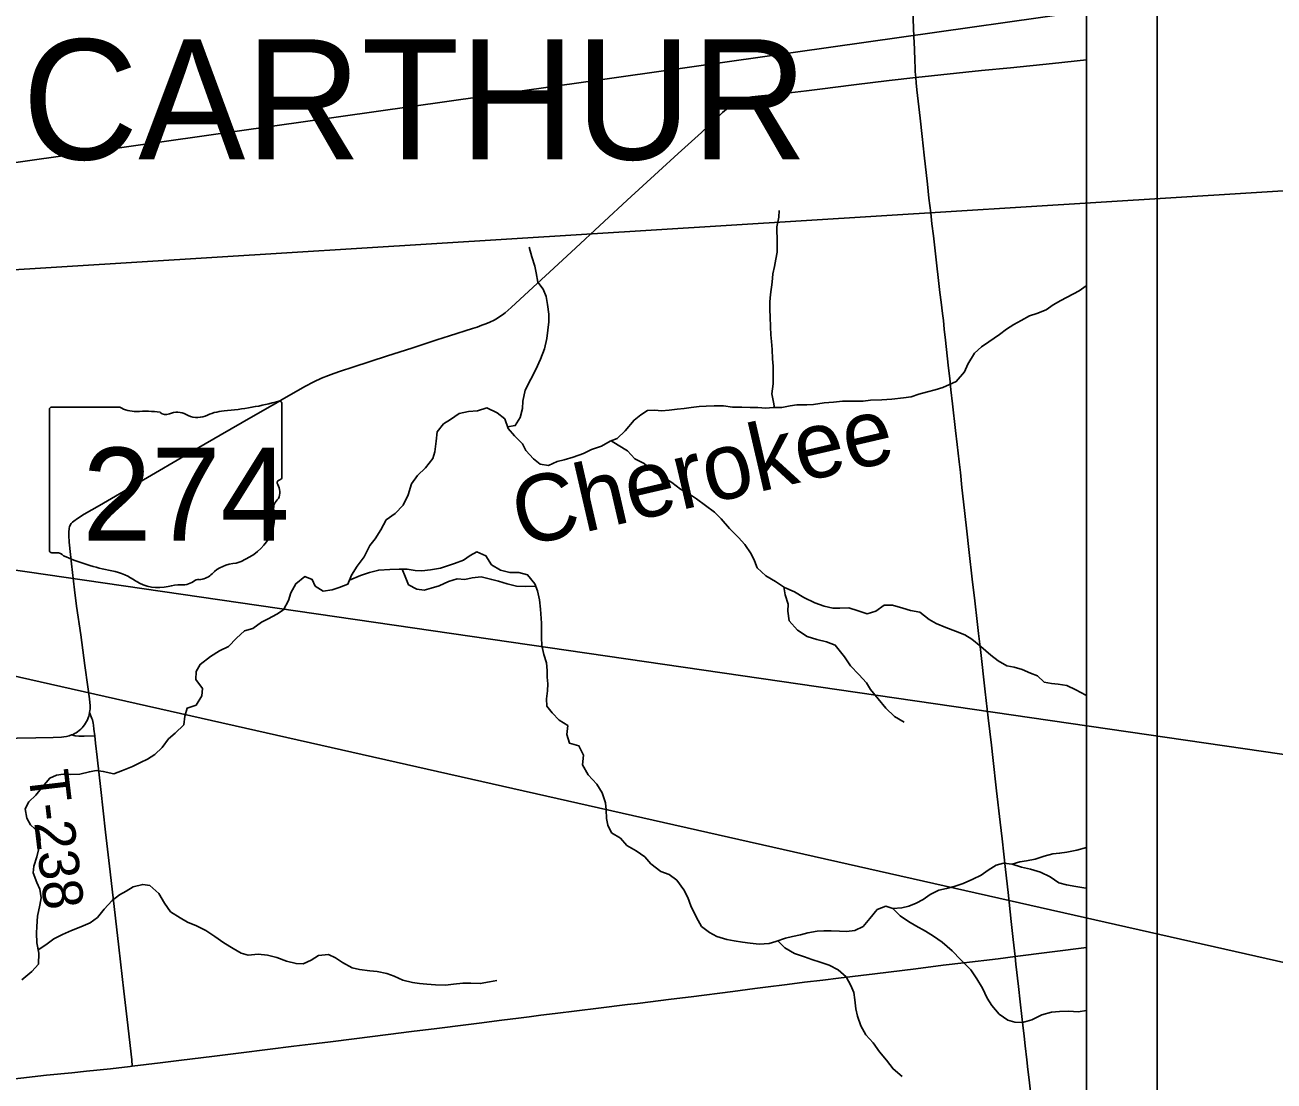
# Model space of a CAD drawing. Extents: x 0 to 34, y -5.4 to 22.
# Drawn here: x 7.394 to 9.166, y 16.492 to 17.991 of the extents above; entities that cross this region are included whole.
import ezdxf

# ---------------------------------------------------------------- set-up
doc = ezdxf.new("R2010")
doc.units = 0
for name, color, linetype in [('GM_X_County_Road', 7, 'Continuous'), ('GM_X_Minor_River', 7, 'Continuous'), ('GM_X_Minor_River_Text', 7, 'Continuous'), ('GM_X_Rail_Line', 7, 'Continuous'), ('GM_X_State_Location', 7, 'Continuous'), ('GM_X_State_Route', 7, 'Continuous'), ('GM_X_State_Shield', 7, 'Continuous'), ('GM_X_Township_Road', 7, 'Continuous'), ('GM_X_Township_Road_Text', 7, 'Continuous'), ('GM_X_Township_Text', 7, 'Continuous'), ('SH_Data', 7, 'Continuous')]:
    doc.layers.add(name, color=color, linetype=linetype)

msp = doc.modelspace()

# ---------------------------------------------------------------- linework, layer by layer
at = {"layer": 'GM_X_County_Road'}
msp.add_lwpolyline([(8.8238, 16.4466), (8.8184, 16.4941), (8.8168, 16.5086), (8.8152, 16.5225), (8.813, 16.542), (8.8114, 16.5558), (8.8096, 16.5717), (8.8082, 16.5836), (8.8058, 16.6046), (8.8035, 16.6265), (8.7997, 16.658), (8.7986, 16.6688), (8.796, 16.6929), (8.7931, 16.7188), (8.7886, 16.7596), (8.7851, 16.7923), (8.7803, 16.8361), (8.7776, 16.8595), (8.7724, 16.9039), (8.7669, 16.9514), (8.7649, 16.9687), (8.7603, 17.0076), (8.756, 17.0446), (8.7494, 17.1045), (8.7467, 17.1273), (8.7436, 17.1526), (8.7423, 17.1652), (8.7414, 17.1736), (8.7377, 17.2044), (8.7334, 17.242), (8.7297, 17.2766), (8.7255, 17.3141), (8.7232, 17.3346), (8.7209, 17.3557), (8.7191, 17.371), (8.7163, 17.3954), (8.7141, 17.4154), (8.7096, 17.4531), (8.7075, 17.4731), (8.7058, 17.4889), (8.7046, 17.4997), (8.7037, 17.508), (8.6998, 17.5432), (8.6981, 17.5589), (8.6968, 17.5711), (8.6956, 17.5814), (8.6936, 17.5973), (8.6919, 17.6111), (8.685, 17.6704), (8.6826, 17.6914), (8.6806, 17.7083), (8.6788, 17.724), (8.6764, 17.745), (8.6743, 17.7647), (8.6695, 17.806), (8.6665, 17.8326), (8.6637, 17.8585), (8.6593, 17.8987), (8.6584, 17.9085), (8.6578, 17.916), (8.6575, 17.9198), (8.657, 17.9248), (8.6567, 17.9301), (8.6563, 17.9396), (8.6557, 17.9564), (8.655, 17.9744), (8.6532, 18.0224)], dxfattribs=at)
at = {"layer": 'GM_X_Minor_River'}
for points in [[(8.4572, 17.4479), (8.4555, 17.4578), (8.4534, 17.4673), (8.4551, 17.4813), (8.4553, 17.4957), (8.4551, 17.5067), (8.4545, 17.517), (8.454, 17.5303), (8.4527, 17.5413), (8.4521, 17.5512), (8.4515, 17.5622), (8.451, 17.5763), (8.4508, 17.5865), (8.4506, 17.5979), (8.4515, 17.6081), (8.4537, 17.6259), (8.455, 17.6377), (8.4571, 17.6479), (8.4591, 17.6585), (8.4608, 17.6683), (8.461, 17.682), (8.4606, 17.704), (8.4635, 17.718), (8.4637, 17.7275)], [(8.0785, 17.4206), (8.0893, 17.4223), (8.0963, 17.4335), (8.0996, 17.4464), (8.1001, 17.457), (8.1034, 17.4725), (8.1112, 17.4879), (8.1183, 17.5019), (8.1253, 17.5165), (8.1308, 17.5313), (8.1341, 17.5456), (8.1371, 17.5695), (8.1369, 17.5805), (8.1349, 17.5942), (8.1332, 17.6056), (8.1288, 17.6159), (8.1214, 17.6259), (8.119, 17.6389), (8.1169, 17.6484), (8.1126, 17.6617), (8.109, 17.6755)], [(8.115, 17.3751), (8.1248, 17.3674), (8.1365, 17.3657), (8.1487, 17.3712), (8.1585, 17.3736), (8.1715, 17.3772), (8.1863, 17.3827), (8.1974, 17.3885), (8.2115, 17.3932), (8.2241, 17.4002), (8.234, 17.4039), (8.2455, 17.4147), (8.2579, 17.43), (8.2674, 17.4375), (8.277, 17.4437), (8.2872, 17.444), (8.297, 17.443), (8.3077, 17.444), (8.319, 17.4453), (8.3289, 17.4467), (8.3391, 17.448), (8.3501, 17.4493), (8.3604, 17.4499), (8.3717, 17.4501), (8.3846, 17.4503), (8.3974, 17.4485), (8.4107, 17.4483), (8.4228, 17.4477), (8.4334, 17.4479), (8.4451, 17.447), (8.4553, 17.4479), (8.4674, 17.4481), (8.4792, 17.4502), (8.4887, 17.4515), (8.503, 17.4517), (8.5125, 17.4523), (8.5277, 17.4543), (8.541, 17.4556), (8.5535, 17.4569), (8.5667, 17.457), (8.583, 17.4571), (8.5936, 17.4581), (8.6095, 17.4589), (8.6235, 17.4598), (8.6402, 17.4618), (8.6512, 17.4632), (8.6622, 17.4668), (8.6744, 17.47), (8.685, 17.4728), (8.6961, 17.4761), (8.7151, 17.4849), (8.7267, 17.4987), (8.7314, 17.5092), (8.7408, 17.525), (8.7508, 17.534), (8.7615, 17.541), (8.7764, 17.5517), (8.7864, 17.5592), (8.7967, 17.5658), (8.807, 17.5713), (8.8192, 17.578), (8.8295, 17.5812), (8.8428, 17.5867), (8.8528, 17.5937), (8.8635, 17.5996), (8.8894, 17.6136), (8.8994, 17.6206), (8.9, 17.621)], [(7.3889, 16.6359), (7.4031, 16.6475), (7.4127, 16.6579), (7.4134, 16.6738), (7.4102, 16.6883), (7.41, 16.702), (7.4106, 16.7115), (7.4112, 16.7263), (7.4145, 16.7418), (7.4165, 16.752), (7.4148, 16.7645), (7.4105, 16.7741), (7.4054, 16.7875), (7.4063, 16.7973), (7.4103, 16.8102), (7.4127, 16.8204), (7.4152, 16.8344), (7.4139, 16.8443), (7.4016, 16.8555), (7.3964, 16.8654), (7.394, 16.8784), (7.3991, 16.8886), (7.4091, 16.8979), (7.4183, 16.9095), (7.4288, 16.9218), (7.4383, 16.9262), (7.4478, 16.9276), (7.4587, 16.927), (7.4712, 16.9276), (7.4849, 16.9311), (7.4948, 16.9329), (7.5046, 16.9315), (7.5197, 16.9283), (7.5319, 16.933), (7.546, 16.9384), (7.5574, 16.9443), (7.5673, 16.9491), (7.5777, 16.9554), (7.5884, 16.9654), (7.5973, 16.9778), (7.6069, 16.986), (7.6188, 16.9975), (7.6202, 17.0097), (7.6238, 17.0214), (7.6363, 17.0257), (7.6445, 17.0389), (7.6454, 17.0491), (7.6361, 17.0618), (7.6363, 17.0732), (7.6422, 17.0833), (7.6567, 17.0948), (7.6697, 17.1026), (7.6823, 17.1088), (7.6935, 17.1204), (7.705, 17.1308), (7.7168, 17.1341), (7.7291, 17.1433), (7.7386, 17.1481), (7.7508, 17.1547), (7.7604, 17.161), (7.7674, 17.1742), (7.771, 17.1851), (7.778, 17.1979), (7.7907, 17.208), (7.8012, 17.204), (7.8056, 17.1944), (7.8168, 17.1874), (7.8297, 17.1891), (7.8392, 17.1923), (7.8518, 17.197), (7.8569, 17.2102), (7.8651, 17.2226), (7.8747, 17.2361), (7.883, 17.2519), (7.8907, 17.2617), (7.8985, 17.2744), (7.9059, 17.2884), (7.9189, 17.2973), (7.9301, 17.3092), (7.9375, 17.3239), (7.9419, 17.3394), (7.9508, 17.3514), (7.9619, 17.3622), (7.9724, 17.3753), (7.9752, 17.3851), (7.9769, 17.3999), (7.9783, 17.4135), (7.9876, 17.4248), (7.9975, 17.4307), (8.0098, 17.4396), (8.023, 17.442), (8.0356, 17.4433), (8.0489, 17.4476), (8.0635, 17.4405), (8.0747, 17.4316), (8.0794, 17.4179), (8.0883, 17.4075), (8.0995, 17.3963), (8.1043, 17.3867), (8.115, 17.3751)], [(8.2256, 17.4008), (8.2353, 17.3944), (8.2484, 17.3862), (8.2588, 17.375), (8.2724, 17.3683), (8.2862, 17.3563), (8.2963, 17.3508), (8.3113, 17.3414), (8.324, 17.3321), (8.3367, 17.3247), (8.3465, 17.3184), (8.3592, 17.3087), (8.3719, 17.2994), (8.3816, 17.2898), (8.3935, 17.2763), (8.4061, 17.2635), (8.415, 17.2535), (8.4243, 17.2404), (8.429, 17.2301), (8.4327, 17.2202), (8.445, 17.209), (8.4585, 17.2011), (8.4716, 17.1926), (8.4855, 17.1862), (8.499, 17.1784), (8.5144, 17.1709), (8.5279, 17.1658), (8.54, 17.1633), (8.5498, 17.1631), (8.5627, 17.1637), (8.5759, 17.1593), (8.5887, 17.1549), (8.6008, 17.1588), (8.6127, 17.1674), (8.6248, 17.1675), (8.6395, 17.1631), (8.65, 17.1599), (8.6632, 17.1574), (8.6767, 17.1473), (8.6868, 17.1414), (8.7004, 17.1355), (8.7139, 17.1307), (8.7274, 17.1252), (8.7372, 17.1193), (8.7499, 17.1088), (8.7641, 17.0965), (8.7745, 17.0883), (8.7869, 17.0813), (8.7975, 17.0796), (8.8088, 17.076), (8.8204, 17.0708), (8.8302, 17.0672), (8.8399, 17.058), (8.8501, 17.0563), (8.8599, 17.0553), (8.872, 17.0536), (8.8847, 17.0473), (8.899, 17.0399), (8.9, 17.0395)], [(7.854, 17.2027), (7.8698, 17.2096), (7.8827, 17.214), (7.8956, 17.2172), (7.9112, 17.2181), (7.9244, 17.2186), (7.9358, 17.2184), (7.9471, 17.2167), (7.9569, 17.2161), (7.969, 17.2174), (7.9831, 17.2199), (7.993, 17.2231), (8.0029, 17.2267), (8.0158, 17.2311), (8.0254, 17.2381), (8.0349, 17.2429), (8.0477, 17.2374), (8.0558, 17.2247), (8.0682, 17.2169), (8.0818, 17.214), (8.0942, 17.2138), (8.1067, 17.2105), (8.1171, 17.1978), (8.1207, 17.1879), (8.1235, 17.175), (8.1252, 17.1616), (8.1264, 17.1419), (8.1266, 17.132), (8.1264, 17.1214), (8.127, 17.1104), (8.1298, 17.0974), (8.1338, 17.0856), (8.1347, 17.0745), (8.1346, 17.0651), (8.1356, 17.0556), (8.135, 17.0457), (8.1337, 17.0343), (8.1343, 17.0241), (8.1417, 17.0145), (8.1514, 17.0044), (8.1638, 16.9966), (8.1624, 16.9837), (8.1664, 16.9715), (8.1796, 16.9679), (8.1862, 16.9548), (8.1848, 16.9408), (8.1929, 16.9266), (8.2052, 16.9135), (8.2125, 16.9013), (8.2176, 16.8871), (8.2182, 16.8772), (8.2188, 16.8647), (8.2205, 16.8552), (8.226, 16.8445), (8.2387, 16.8366), (8.2477, 16.8266), (8.2608, 16.8188), (8.2731, 16.8102), (8.2817, 16.8006), (8.2959, 16.7894), (8.3079, 16.7854), (8.3188, 16.7772), (8.3284, 16.7637), (8.3343, 16.7526), (8.3386, 16.7408), (8.3467, 16.7243), (8.3536, 16.7117), (8.3648, 16.7028), (8.3754, 16.6973), (8.3897, 16.6928), (8.3999, 16.6912), (8.4119, 16.6894), (8.4225, 16.6877), (8.4354, 16.6864), (8.4494, 16.6873), (8.4593, 16.6901), (8.473, 16.6948), (8.4828, 16.6973), (8.4939, 16.6998), (8.5045, 16.7027), (8.5178, 16.7047), (8.5272, 16.7053), (8.5375, 16.7055), (8.5496, 16.7049), (8.5594, 16.7044), (8.5711, 16.7057), (8.583, 16.7116), (8.5926, 16.7228), (8.603, 16.7355), (8.6152, 16.7402), (8.625, 16.737), (8.6379, 16.738), (8.6478, 16.7404), (8.6584, 16.7448), (8.668, 16.7496), (8.6779, 16.757), (8.6905, 16.7629), (8.7012, 16.7653), (8.7122, 16.7682), (8.7247, 16.7725), (8.7385, 16.7788)], [(7.929, 17.2185), (7.9329, 17.2082), (7.9377, 17.1963), (7.9497, 17.1901), (7.9599, 17.1888), (7.9698, 17.1916), (7.9815, 17.1948), (7.9945, 17.2011), (8.0071, 17.2047), (8.0176, 17.2037), (8.0283, 17.2062), (8.0408, 17.2075), (8.0559, 17.2038), (8.0657, 17.2014), (8.0777, 17.1978), (8.0909, 17.1945), (8.1038, 17.1939), (8.1183, 17.1944)], [(8.4702, 17.1935), (8.4725, 17.1819), (8.4765, 17.1686), (8.476, 17.1591), (8.478, 17.1454), (8.4899, 17.1319), (8.5037, 17.1229), (8.5173, 17.1185), (8.5309, 17.1152), (8.5433, 17.1105), (8.5566, 17.0939), (8.5648, 17.0813), (8.577, 17.0689), (8.5878, 17.0573), (8.5933, 17.0477), (8.6041, 17.0343), (8.6152, 17.0212), (8.6275, 17.0096), (8.641, 17.0014)], [(8.7944, 16.7998), (8.8055, 16.803), (8.815, 16.8048), (8.8271, 16.8072), (8.84, 16.8112), (8.8522, 16.8144), (8.8617, 16.8154), (8.8719, 16.8171), (8.886, 16.8199), (8.9, 16.8237)], [(8.7385, 16.7788), (8.7503, 16.7842), (8.7602, 16.7913), (8.7717, 16.7987), (8.782, 16.8012), (8.7944, 16.7998), (8.8076, 16.7958), (8.8204, 16.7929), (8.8347, 16.7885), (8.8483, 16.7818), (8.8606, 16.7736), (8.8715, 16.7704), (8.8848, 16.7683), (8.8991, 16.7661), (8.9, 16.766)], [(7.4123, 16.6785), (7.423, 16.6855), (7.4345, 16.694), (7.4467, 16.7002), (7.4597, 16.7057), (7.4726, 16.7108), (7.4863, 16.7166), (7.4967, 16.7244), (7.506, 16.736), (7.5171, 16.7484), (7.5275, 16.7565), (7.5374, 16.7617), (7.547, 16.7676), (7.5606, 16.7712), (7.5708, 16.7695), (7.5835, 16.7582), (7.5916, 16.7448), (7.6001, 16.7325), (7.6136, 16.7236), (7.6241, 16.7177), (7.6369, 16.7122), (7.65, 16.7059), (7.6631, 16.6973), (7.6759, 16.6883), (7.689, 16.6802), (7.7002, 16.6735), (7.7104, 16.6707), (7.7244, 16.672), (7.7376, 16.6706), (7.7512, 16.6673), (7.7647, 16.6625), (7.7783, 16.6589), (7.7885, 16.6587), (7.7996, 16.6638), (7.8103, 16.6705), (7.8243, 16.6718), (7.8341, 16.667), (7.8442, 16.6604), (7.8581, 16.653), (7.8682, 16.6505), (7.883, 16.6487), (7.8935, 16.6474), (7.9071, 16.6449), (7.9173, 16.641), (7.9297, 16.6354), (7.9436, 16.6318), (7.9534, 16.6308), (7.9636, 16.6295), (7.9761, 16.6286), (7.9905, 16.6283), (8.0019, 16.6296), (8.0151, 16.6313), (8.0265, 16.6311), (8.0397, 16.6305), (8.0526, 16.6329), (8.0633, 16.6347)], [(8.625, 16.737), (8.6354, 16.7266), (8.6474, 16.7184), (8.6579, 16.7126), (8.6714, 16.7047), (8.6827, 16.6977), (8.695, 16.6891), (8.7092, 16.6771), (8.7218, 16.664), (8.7356, 16.6501), (8.7445, 16.637), (8.7522, 16.624), (8.7592, 16.6098), (8.7658, 16.5995), (8.7758, 16.5872), (8.7882, 16.5786), (8.7984, 16.5758), (8.8093, 16.5752), (8.8223, 16.5792), (8.8364, 16.5861), (8.8501, 16.5901), (8.8618, 16.591), (8.8747, 16.5912), (8.8879, 16.5906), (8.8997, 16.5923)], [(8.4619, 16.6911), (8.472, 16.6812), (8.4855, 16.6734), (8.4998, 16.6682), (8.5103, 16.6646), (8.522, 16.661), (8.5348, 16.6566), (8.5475, 16.6499), (8.5587, 16.6402), (8.5657, 16.6276), (8.5697, 16.618), (8.5714, 16.6074), (8.5727, 16.5948), (8.5748, 16.5842), (8.5795, 16.5704), (8.5869, 16.5578), (8.5973, 16.5466), (8.6062, 16.5335), (8.6162, 16.522), (8.6255, 16.5093), (8.6385, 16.4988)]]:
    msp.add_lwpolyline(points, dxfattribs=at)
at = {"layer": 'GM_X_Rail_Line'}
msp.add_lwpolyline([(8.9, 15.5944), (8.9, 19.2127), (8.5201, 19.1691), (7.2315, 19.0156), (6.9054, 18.9823), (6.6792, 18.9603), (6.4496, 18.9373), (6.0045, 18.8908), (5.7334, 18.8597), (5.7313, 18.8595), (5.378, 18.814), (5.096, 18.7806), (5.0255, 18.7742), (4.7505, 18.7432), (3.5131, 18.6037), (3.3669, 18.5872), (3.3607, 18.5226), (3.3599, 18.5136), (3.2432, 17.2942), (3.13, 16.1326)], dxfattribs=at)
at = {"layer": 'GM_X_State_Route'}
msp.add_lwpolyline([(7.3554, 16.9784), (7.4089, 16.9791), (7.4337, 16.9796), (7.4454, 16.9803), (7.4489, 16.9806), (7.4527, 16.9811), (7.4564, 16.9819), (7.4596, 16.9832), (7.462, 16.9841), (7.4639, 16.9852), (7.4662, 16.9864), (7.468, 16.9876), (7.4706, 16.9897), (7.4726, 16.9914), (7.4746, 16.9935), (7.4762, 16.9954), (7.478, 16.9977), (7.4795, 17), (7.4809, 17.0024), (7.4821, 17.0049), (7.4832, 17.0074), (7.4841, 17.0097), (7.4847, 17.012), (7.4852, 17.0149), (7.4857, 17.018), (7.4859, 17.0199), (7.486, 17.0217), (7.4859, 17.0247), (7.485, 17.0345), (7.4828, 17.0517), (7.4787, 17.0819), (7.4726, 17.1255), (7.4667, 17.1661), (7.4639, 17.189), (7.4598, 17.226), (7.4565, 17.2567), (7.4559, 17.2662), (7.4557, 17.2695), (7.4558, 17.2724), (7.4561, 17.2746), (7.4565, 17.2769), (7.4569, 17.2788), (7.4579, 17.281), (7.4592, 17.2832), (7.4611, 17.285), (7.463, 17.2866), (7.4682, 17.2904), (7.4778, 17.2964), (7.4993, 17.309), (7.5391, 17.3319), (7.5789, 17.355), (7.6405, 17.3911), (7.6706, 17.4086), (7.7019, 17.4265), (7.7406, 17.4488), (7.7489, 17.4537), (7.7584, 17.4592), (7.7907, 17.4779), (7.8034, 17.4845), (7.8142, 17.4894), (7.8241, 17.4935), (7.832, 17.4963), (7.8413, 17.4994), (7.8589, 17.5051), (7.9078, 17.5211), (7.9427, 17.5323), (7.9782, 17.5437), (7.9959, 17.5494), (8.0284, 17.5598), (8.0352, 17.5621), (8.0419, 17.5645), (8.0477, 17.5667), (8.0531, 17.5689), (8.0594, 17.5719), (8.0641, 17.5748), (8.0673, 17.577), (8.0712, 17.5796), (8.0748, 17.5824), (8.0791, 17.5858), (8.0837, 17.59), (8.1147, 17.6187), (8.1321, 17.6347), (8.1686, 17.6685), (8.2156, 17.7119), (8.2479, 17.7419), (8.2924, 17.7826), (8.3204, 17.8082), (8.3534, 17.8383), (8.3834, 17.8663), (8.3947, 17.8761), (8.3976, 17.8784), (8.4002, 17.8803), (8.4028, 17.8819), (8.4051, 17.8831), (8.4077, 17.8842), (8.4098, 17.8852), (8.4121, 17.8861), (8.4144, 17.8869), (8.4168, 17.8875), (8.4188, 17.8879), (8.4251, 17.8886), (8.4573, 17.892), (8.4783, 17.8944), (8.5024, 17.8972), (8.5215, 17.8996), (8.5698, 17.9058), (8.6197, 17.9118), (8.6578, 17.916), (8.7511, 17.9259), (8.7919, 17.93), (8.8519, 17.9361), (8.9, 17.9411)], dxfattribs=at)
at = {"layer": 'GM_X_State_Shield'}
for p, q in [((7.4285, 17.4451), (7.4285, 17.245)), ((7.5282, 17.4485), (7.4317, 17.4485)), ((7.758, 17.3488), (7.758, 17.4535)), ((7.758, 17.3488), (7.758, 17.3488))]:
    msp.add_line(p, q, dxfattribs=at)
for centre, major_axis, start_param, end_param in [((7.4322, 17.4455), (0.00382, 0), 1.712693, 3.28349), ((7.5512, 17.4717), (0.037, 0), 4.042523, 4.731795), ((7.5635, 17.3362), (0.133, 0), 1.404758, 1.657858), ((7.5937, 17.4465), (0.0107, 0), 3.836095, 5.185415), ((7.6094, 17.4234), (0.0222, 0), 0.950623, 2.079405), ((7.6852, 17.3874), (0.0703, 0), 1.699011, 2.107814), ((7.6406, 17.7213), (0.3495, 0), 4.814394, 5.042369), ((7.7544, 17.4539), (0.00367, 0), 6.141152, 7.989035), ((7.638, 17.4551), (0.0267, 0), 4.081561, 5.145723), ((7.7572, 17.3411), (0.00568, 0), 1.883978, 3.671073), ((7.7211, 17.3279), (0.0341, 0), 5.934695, 6.695948), ((7.7541, 17.3484), (0.00393, 0), 5.05454, 6.418171), ((7.7712, 17.305), (0.0248, 0), 2.387724, 3.262537), ((7.6602, 17.2917), (0.0874, 0), 5.101752, 6.440018), ((7.4323, 17.2445), (0.00385, 0), 3.00124, 4.508301), ((7.4329, 17.265), (0.0294, 0), 4.665946, 4.897461), ((7.4389, 17.2334), (0.0106, 0), 0.519207, 1.627899), ((7.5727, 17.4132), (0.2524, 0), 4.195997, 4.488961), ((7.4974, 17.155), (0.079, 0), 0.823519, 1.323587), ((7.6364, 17.2256), (0.0282, 0), 4.937069, 5.64225), ((7.6971, 17.1888), (0.0479, 0), 1.647645, 2.488434), ((7.5829, 17.2324), (0.0501, 0), 4.026481, 4.996735), ((7.6118, 17.1632), (0.0412, 0), 1.495662, 1.94098), ((7.6155, 17.2174), (0.0267, 0), 4.691044, 5.507374), ((7.6396, 17.198), (0.00752, 0), 1.147584, 2.315152)]:
    msp.add_ellipse(centre, major_axis=major_axis, ratio=0.8, start_param=start_param, end_param=end_param, dxfattribs=at)
at = {"layer": 'GM_X_Township_Road'}
msp.add_line((8.7986, 16.6688), (8.9, 16.6818), dxfattribs=at)
for points in [[(7.5459, 16.5131), (7.5452, 16.5222), (7.5385, 16.5794), (7.534, 16.6197), (7.5267, 16.6821), (7.5219, 16.7231), (7.5146, 16.789), (7.508, 16.8453), (7.501, 16.9058), (7.4958, 16.9517), (7.4937, 16.9715), (7.4925, 16.9822), (7.4914, 16.9916), (7.4908, 16.9972), (7.4904, 17), (7.49, 17.0022), (7.4894, 17.0049), (7.4886, 17.0068), (7.4852, 17.0149)], [(7.4596, 16.9832), (7.4646, 16.9822), (7.47, 16.9815), (7.4777, 16.9815), (7.4925, 16.9822)], [(7.5459, 16.5131), (7.5853, 16.5178), (7.6155, 16.5218), (7.6586, 16.5271), (7.7004, 16.5323), (7.7375, 16.5369), (7.7751, 16.5416), (7.7991, 16.5446), (7.8269, 16.5479), (7.8608, 16.5522), (7.9088, 16.558), (7.9421, 16.5623), (7.9779, 16.5666), (8.0192, 16.572), (8.0383, 16.5745), (8.0703, 16.5785), (8.0937, 16.5815), (8.1091, 16.5834), (8.1258, 16.5856), (8.1461, 16.5881), (8.2072, 16.5954), (8.2485, 16.6006), (8.2626, 16.6024), (8.3107, 16.6083), (8.3391, 16.6118), (8.3981, 16.6192), (8.4295, 16.6233), (8.4443, 16.6252), (8.4751, 16.629), (8.4997, 16.6323), (8.5256, 16.6354), (8.5478, 16.6382), (8.5996, 16.6445), (8.6579, 16.6514), (8.6967, 16.6565), (8.726, 16.6599), (8.7746, 16.6657), (8.7986, 16.6688)], [(7.329, 16.49), (7.3525, 16.4927), (7.3877, 16.4964), (7.4242, 16.5004), (7.46, 16.504), (7.481, 16.5063), (7.515, 16.5097), (7.5428, 16.5127), (7.5459, 16.5131)]]:
    msp.add_lwpolyline(points, dxfattribs=at)
at = {"layer": 'SH_Data'}
for p, q in [((9, 21), (9, 14)), ((8.9, 20.9), (8.9, 14.1))]:
    msp.add_line(p, q, dxfattribs=at)
for points in [[(9.2327, 18.0581), (5.4613, 17.524), (9.2327, 17.7586)], [(9.2327, 16.948), (5.505, 17.4894), (9.2327, 16.6485)]]:
    msp.add_lwpolyline(points, close=True, dxfattribs=at)

# ---------------------------------------------------------------- texts
at = {"layer": 'GM_X_Minor_River_Text'}
msp.add_text('Cherokee', height=0.0947, rotation=13.0356, dxfattribs=at).set_placement((8.0974, 17.2497))
at = {"layer": 'GM_X_State_Location'}
msp.add_text('274', height=0.000189, rotation=0, dxfattribs=at).set_placement((7.5227, 17.3179))
for s, p in [('s', (7.5896, 17.3317)), ('r', (7.5895, 17.3317))]:
    msp.add_text(s, height=0.000189, dxfattribs=at).set_placement(p)
at = {"layer": 'GM_X_State_Shield'}
msp.add_text('274', height=0.13184, dxfattribs=at).set_placement((7.475, 17.2591))
at = {"layer": 'GM_X_Township_Road_Text'}
msp.add_text('T-238', height=0.05682, rotation=276.7432, dxfattribs=at).set_placement((7.3981, 16.9302))
at = {"layer": 'GM_X_Township_Text'}
msp.add_text('MCARTHUR', height=0.17045, rotation=0, dxfattribs=at).set_placement((7.1998, 17.7998))

doc.saveas('drawing.dxf')
